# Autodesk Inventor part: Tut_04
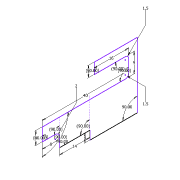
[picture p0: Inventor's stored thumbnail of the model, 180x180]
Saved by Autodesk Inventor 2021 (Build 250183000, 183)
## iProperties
Created: 2019-02
Part Number: Tut_04
Material: Generic
Document SubType Name: Modeling
Designer: LENOVO-CADCIM
Density: 1 g/cm^3
Appearance: Default
Author: LENOVO-CADCIM
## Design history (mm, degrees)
sketch "Sketch1"
  geometry: L1 (0, 0)-(0, 22); L2 (0, 0)-(22, 0); L3 (0, 22)-(4, 22); L4 (4, 22)-(4, 36); L5 (4, 22)-(18, 22); L6 (4, 36)-(8.333, 36); L7 (10.333, 38)-(10.333, 44); L8 (10.333, 36)-(16.333, 36); L9 (10.333, 44)-(16.333, 44); L10 (16.333, 44)-(16.333, 5.5); L11 (17.833, 4)-(23.833, 4); L12 (25.333, 5.5)-(25.333, 20); L13 (25.333, 20)-(30.333, 20); L14 (30.333, 20)-(30.333, 0); L15 (30.333, 0)-(0, 0); A1 r 2 centre (8.333, 38) between (8.333, 36) and (10.333, 38); A2 r 1.5 centre (23.833, 5.5) between (23.833, 4) and (25.333, 5.5); A3 r 1.5 centre (17.833, 5.5) between (16.333, 5.5) and (17.833, 4); 2 further points
  constraints: 30 end point, 9 perpendicular, 6 point on circle, 6 point on line, 6 tangent, 3 centre point, 3 horizontal, 2 vertical
  dimensions: "d0" = 90 deg angle of L2 L1; "d1" = 4 distance of L1.end L3.end; "d3" = 14 distance of L3.end L4.end; "d4" = 90 deg angle of L5 L4 (derived); "d5" = 90 deg angle of L4 L6; "d6" = 8 distance of L8.start L7.end; "d7" = 90 deg angle of L8 L7 (derived); "d8" = 6 distance of L7.end L9.end; "d9" = 90 deg angle of L7 L9 (derived); "d10" = 40 distance of L9.end point (16.333, 4); "d11" = 90 deg angle of L9 L10 (derived); "d12" = 9 distance of point (16.333, 4) point (25.333, 4); "d13" = 90 deg angle of L11 L10 (derived); "d14" = 16 distance of point (25.333, 4) L12.end; "d15" = 90 deg angle of L12 L11 (derived); "d16" = 5 distance of L12.end L13.end; "d17" = 90 deg angle of L12 L13 (derived); "d18" = 2 radius of A1 (derived); "d19" = 1.5 radius of A2 (derived); "d20" = 1.5 radius of A3 (derived)
